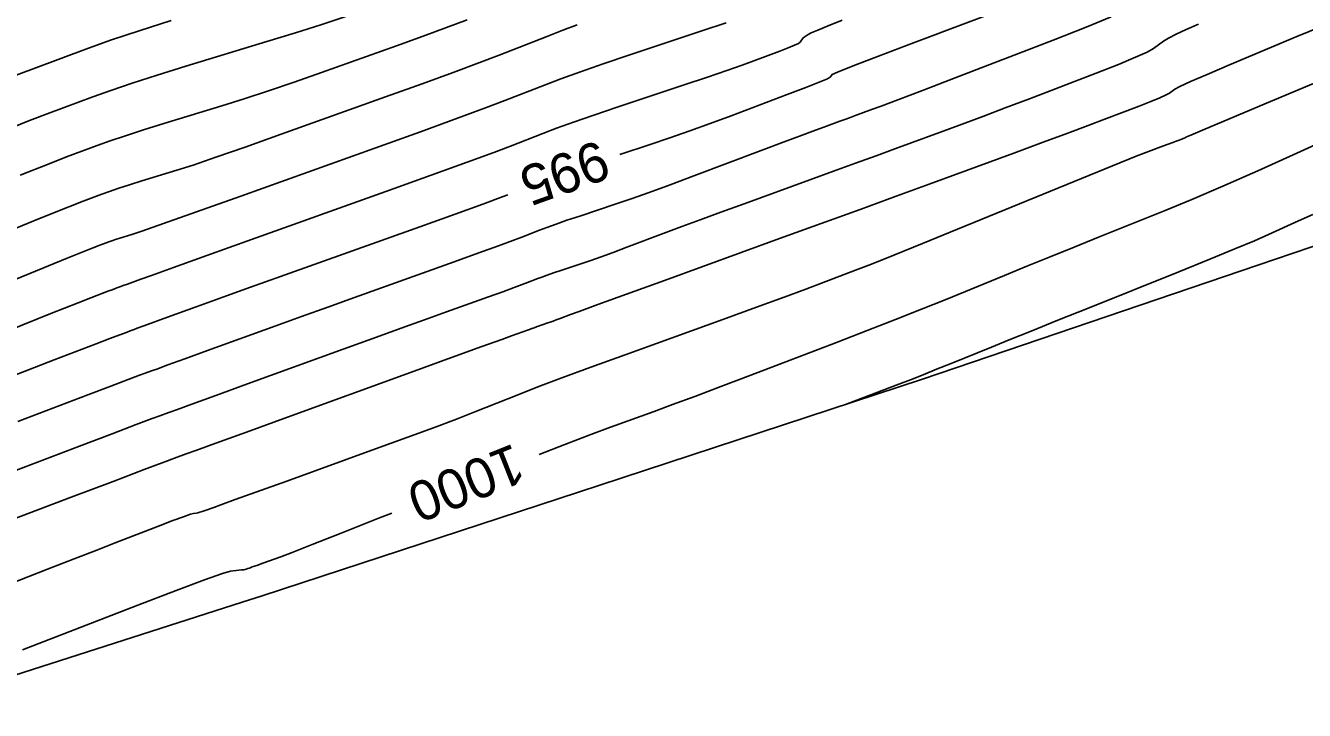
# Model space of a CAD drawing. Extents: x 2175772 to 2185556, y 721391 to 722853.
# Drawn here: x 2178632.3 to 2178722.5, y 721747 to 721795.3 of the extents above; entities that cross this region are included whole.
import ezdxf

# ---------------------------------------------------------------- set-up
doc = ezdxf.new("R2010")
doc.units = 0
for name, color, linetype in [('DT_X_Contour_Major', 7, 'Continuous'), ('DT_X_Contour_Minor', 7, 'Continuous'), ('DT_X_TIN_Hull', 7, 'Continuous')]:
    doc.layers.add(name, color=color, linetype=linetype)

msp = doc.modelspace()

# ---------------------------------------------------------------- linework, layer by layer
at = {"layer": 'DT_X_Contour_Major'}
for points in [[(2178660.661, 721798.004), (2178660.335, 721797.884), (2178659.194, 721797.473), (2178655.973, 721796.321), (2178654.649, 721795.861), (2178653.092, 721795.346), (2178651.302, 721794.775), (2178649.279, 721794.149), (2178643.573, 721792.406), (2178641.558, 721791.781), (2178639.793, 721791.214), (2178638.279, 721790.704), (2178637.014, 721790.251), (2178633.975, 721789.121), (2178632.542, 721788.572), (2178630.52, 721787.772)], [(2178702.475, 721796.913), (2178694.915, 721794.072), (2178692.429, 721793.132), (2178690.642, 721792.444), (2178689.553, 721792.006), (2178689.162, 721791.819), (2178689.053, 721791.657), (2178688.831, 721791.533), (2178688.248, 721791.285), (2178687.303, 721790.912), (2178685.998, 721790.415), (2178682.034, 721788.922), (2178680.563, 721788.376), (2178679.121, 721787.855), (2178677.71, 721787.361), (2178676.328, 721786.893), (2178674.191, 721786.181)], [(2178729.674, 721789.794), (2178721.955, 721786.277), (2178719.203, 721785.035), (2178716.736, 721783.947), (2178714.553, 721783.012), (2178712.654, 721782.23), (2178707.971, 721780.352), (2178706.238, 721779.655), (2178704.552, 721778.973), (2178702.912, 721778.306), (2178701.319, 721777.655), (2178697.132, 721775.939), (2178695.476, 721775.268), (2178693.647, 721774.542), (2178691.645, 721773.761), (2178689.47, 721772.924), (2178683.44, 721770.621), (2178681.318, 721769.813), (2178679.472, 721769.117), (2178677.902, 721768.532), (2178676.61, 721768.059), (2178673.533, 721766.947), (2178672.148, 721766.432), (2178670.302, 721765.724), (2178668.509, 721765.022)], [(2178666.288, 721783.342), (2178665.963, 721783.218), (2178664.525, 721782.69), (2178662.567, 721781.981), (2178660.089, 721781.091), (2178650.256, 721777.572), (2178648.14, 721776.813), (2178646.44, 721776.202), (2178645.155, 721775.737), (2178642.282, 721774.694), (2178640.615, 721774.089), (2178640.147, 721773.919), (2178639.923, 721773.838), (2178639.65, 721773.739), (2178639.423, 721773.654), (2178638.214, 721773.197), (2178637.234, 721772.825), (2178634.285, 721771.705), (2178632.884, 721771.163), (2178630.893, 721770.378)], [(2178658.1, 721760.886), (2178657.223, 721760.537), (2178654.539, 721759.47), (2178652.485, 721758.659), (2178651.061, 721758.103), (2178650.269, 721757.803), (2178648.997, 721757.344), (2178648.574, 721757.191), (2178648.259, 721757.077), (2178648.051, 721757.002), (2178647.951, 721756.966), (2178647.828, 721756.922), (2178647.761, 721756.904), (2178647.651, 721756.885), (2178647.499, 721756.865), (2178647.305, 721756.843), (2178646.731, 721756.783), (2178646.161, 721756.615), (2178644.881, 721756.159), (2178642.892, 721755.414), (2178640.192, 721754.38), (2178632.048, 721751.237)]]:
    msp.add_lwpolyline(points, dxfattribs=at)
at = {"layer": 'DT_X_Contour_Minor'}
for points in [[(2178723.694, 721795.222), (2178721.965, 721794.511), (2178717.199, 721792.505), (2178715.617, 721791.834), (2178714.448, 721791.325), (2178713.69, 721790.98), (2178713.344, 721790.796), (2178712.972, 721790.524), (2178712.733, 721790.39), (2178712.295, 721790.192), (2178711.658, 721789.929), (2178710.823, 721789.602), (2178708.329, 721788.645), (2178707.232, 721788.228), (2178705.808, 721787.696), (2178704.058, 721787.048), (2178701.983, 721786.285), (2178696.014, 721784.096), (2178693.675, 721783.24), (2178691.135, 721782.313), (2178688.395, 721781.315), (2178685.455, 721780.246), (2178677.346, 721777.303), (2178674.65, 721776.324), (2178672.645, 721775.595), (2178671.332, 721775.115), (2178670.709, 721774.886), (2178669.97, 721774.608), (2178669.708, 721774.51), (2178669.479, 721774.426), (2178669.282, 721774.356), (2178669.116, 721774.299), (2178668.718, 721774.167), (2178668.578, 721774.12), (2178668.457, 721774.078), (2178668.357, 721774.042), (2178668.275, 721774.011), (2178668.083, 721773.936), (2178667.983, 721773.898), (2178667.826, 721773.84), (2178667.612, 721773.762), (2178667.341, 721773.665), (2178666.542, 721773.379), (2178665.873, 721773.138), (2178664.464, 721772.627), (2178662.315, 721771.848), (2178659.427, 721770.8), (2178650.738, 721767.646), (2178647.848, 721766.597), (2178645.696, 721765.815), (2178644.281, 721765.302), (2178643.603, 721765.055), (2178642.778, 721764.756), (2178642.09, 721764.499), (2178640.642, 721763.953), (2178638.436, 721763.117), (2178635.471, 721761.992), (2178626.552, 721758.605)], [(2178681.683, 721795.471), (2178679.972, 721794.901), (2178674.827, 721793.188), (2178673.008, 721792.575), (2178671.409, 721792.02), (2178670.031, 721791.522), (2178668.873, 721791.082), (2178666.079, 721789.987), (2178664.719, 721789.469), (2178662.737, 721788.737), (2178660.131, 721787.792), (2178656.902, 721786.632), (2178647.461, 721783.254), (2178644.324, 721782.133), (2178641.993, 721781.306), (2178640.468, 721780.771), (2178639.75, 721780.528), (2178638.91, 721780.271), (2178638.613, 721780.179), (2178638.354, 721780.096), (2178638.131, 721780.021), (2178637.944, 721779.954), (2178637.497, 721779.788), (2178636.838, 721779.524), (2178635.198, 721778.859), (2178632.575, 721777.791), (2178628.971, 721776.321)], [(2178715.024, 721795.386), (2178714.142, 721795.004), (2178713.436, 721794.677), (2178712.907, 721794.403), (2178712.555, 721794.184), (2178711.852, 721793.67), (2178711.4, 721793.417), (2178710.574, 721793.042), (2178709.371, 721792.546), (2178707.794, 721791.929), (2178703.087, 721790.122), (2178701.383, 721789.47), (2178699.801, 721788.871), (2178698.342, 721788.325), (2178697.005, 721787.83), (2178693.603, 721786.583), (2178692.27, 721786.095), (2178690.823, 721785.567), (2178689.261, 721784.998), (2178687.586, 721784.389), (2178682.964, 721782.711), (2178681.319, 721782.113), (2178679.85, 721781.574), (2178678.556, 721781.095), (2178677.438, 721780.677), (2178674.691, 721779.643), (2178673.72, 721779.28), (2178672.868, 721778.968), (2178672.135, 721778.707), (2178671.52, 721778.497), (2178670.039, 721778.004), (2178669.52, 721777.829), (2178669.073, 721777.675), (2178668.698, 721777.54), (2178668.395, 721777.425), (2178667.682, 721777.146), (2178667.31, 721777.004), (2178666.725, 721776.79), (2178665.93, 721776.502), (2178664.923, 721776.14), (2178661.957, 721775.079), (2178660.667, 721774.616), (2178659.023, 721774.023), (2178657.024, 721773.299), (2178654.67, 721772.445), (2178647.919, 721769.995), (2178645.675, 721769.18), (2178644.002, 721768.573), (2178642.903, 721768.174), (2178642.376, 721767.983), (2178641.736, 721767.75), (2178641.201, 721767.551), (2178640.076, 721767.126), (2178638.362, 721766.477), (2178636.058, 721765.603), (2178629.13, 721762.972)], [(2178671.176, 721795.334), (2178670.16, 721794.95), (2178668.992, 721794.497), (2178665.678, 721793.197), (2178664.245, 721792.647), (2178662.432, 721791.972), (2178660.239, 721791.171), (2178657.666, 721790.246), (2178650.299, 721787.61), (2178647.766, 721786.709), (2178645.693, 721785.986), (2178644.08, 721785.439), (2178642.926, 721785.068), (2178640.464, 721784.316), (2178639.595, 721784.047), (2178638.834, 721783.802), (2178638.18, 721783.582), (2178637.634, 721783.386), (2178636.323, 721782.899), (2178635.308, 721782.5), (2178633.247, 721781.67), (2178630.141, 721780.409)], [(2178689.867, 721795.661), (2178688.881, 721795.262), (2178688.155, 721794.961), (2178687.689, 721794.76), (2178687.482, 721794.658), (2178687.125, 721794.414), (2178686.924, 721794.116), (2178686.801, 721794.028), (2178686.518, 721793.892), (2178686.074, 721793.707), (2178685.47, 721793.473), (2178683.646, 721792.786), (2178682.825, 721792.487), (2178681.733, 721792.105), (2178680.368, 721791.639), (2178678.732, 721791.091), (2178674.004, 721789.517), (2178672.346, 721788.959), (2178670.919, 721788.464), (2178669.721, 721788.034), (2178668.753, 721787.668), (2178666.48, 721786.777), (2178665.29, 721786.325), (2178663.425, 721785.64), (2178660.886, 721784.72), (2178657.672, 721783.567), (2178648.201, 721780.178), (2178645.05, 721779.051), (2178642.699, 721778.209), (2178641.148, 721777.653), (2178640.398, 721777.383), (2178639.464, 721777.044), (2178639.153, 721776.931), (2178638.921, 721776.847), (2178638.769, 721776.791), (2178638.696, 721776.765), (2178638.608, 721776.733), (2178638.534, 721776.705), (2178638.378, 721776.646), (2178638.141, 721776.557), (2178637.822, 721776.436), (2178636.863, 721776.071), (2178635.98, 721775.724), (2178634.052, 721774.953), (2178631.079, 721773.76)], [(2178642.54, 721795.649), (2178640.273, 721794.92), (2178638.328, 721794.265), (2178636.704, 721793.684), (2178632.801, 721792.232), (2178631.158, 721791.608)], [(2178708.852, 721795.892), (2178707.085, 721795.163), (2178704.765, 721794.256), (2178697.844, 721791.598), (2178695.533, 721790.712), (2178693.794, 721790.046), (2178692.625, 721789.601), (2178692.027, 721789.376), (2178691.192, 721789.07), (2178690.866, 721788.95), (2178690.511, 721788.82), (2178690.128, 721788.681), (2178689.716, 721788.532), (2178688.583, 721788.12), (2178687.988, 721787.901), (2178687.054, 721787.553), (2178685.78, 721787.075), (2178684.167, 721786.469), (2178679.412, 721784.678), (2178677.732, 721784.05), (2178676.257, 721783.511), (2178674.988, 721783.059), (2178673.924, 721782.695), (2178671.361, 721781.842), (2178670.462, 721781.539), (2178669.688, 721781.271), (2178669.039, 721781.038), (2178668.514, 721780.839), (2178667.281, 721780.356), (2178666.636, 721780.111), (2178665.625, 721779.74), (2178664.249, 721779.241), (2178662.506, 721778.616), (2178657.372, 721776.779), (2178655.462, 721776.094), (2178653.582, 721775.418), (2178651.732, 721774.75), (2178649.912, 721774.091), (2178645.101, 721772.345), (2178643.501, 721771.764), (2178642.309, 721771.331), (2178641.525, 721771.047), (2178641.15, 721770.91), (2178640.693, 721770.744), (2178640.312, 721770.602), (2178639.51, 721770.3), (2178638.288, 721769.837), (2178636.646, 721769.214), (2178631.707, 721767.338)], [(2178663.41, 721795.684), (2178661.967, 721795.144), (2178660.307, 721794.536), (2178658.43, 721793.859), (2178653.136, 721791.965), (2178651.208, 721791.285), (2178649.392, 721790.666), (2178647.691, 721790.107), (2178646.103, 721789.609), (2178642.019, 721788.361), (2178640.577, 721787.914), (2178639.313, 721787.508), (2178638.229, 721787.143), (2178637.324, 721786.819), (2178635.149, 721786.01), (2178633.925, 721785.536), (2178631.884, 721784.721)], [(2178726.317, 721792.546), (2178719.373, 721789.623), (2178717.092, 721788.663), (2178715.459, 721787.974), (2178714.473, 721787.556), (2178714.134, 721787.409), (2178714.092, 721787.378), (2178714.065, 721787.363), (2178714.016, 721787.341), (2178713.945, 721787.312), (2178713.851, 721787.275), (2178713.572, 721787.168), (2178713.429, 721787.114), (2178713.209, 721787.032), (2178712.536, 721786.785), (2178710.607, 721786.077), (2178698.01, 721780.913), (2178695.536, 721779.902), (2178693.512, 721779.082), (2178691.94, 721778.453), (2178690.818, 721778.015), (2178688.427, 721777.101), (2178687.319, 721776.685), (2178685.789, 721776.12), (2178683.836, 721775.407), (2178681.461, 721774.546), (2178674.563, 721772.053), (2178672.155, 721771.176), (2178670.102, 721770.419), (2178668.406, 721769.779), (2178667.067, 721769.257), (2178663.969, 721768.024), (2178662.66, 721767.513), (2178661.054, 721766.906), (2178659.151, 721766.203), (2178656.952, 721765.404), (2178650.693, 721763.144), (2178647.059, 721761.832), (2178646.036, 721761.463), (2178645.544, 721761.285), (2178644.938, 721761.066), (2178644.728, 721760.993), (2178644.556, 721760.939), (2178644.42, 721760.903), (2178644.321, 721760.885), (2178644.104, 721760.862), (2178643.89, 721760.799), (2178643.408, 721760.627), (2178642.659, 721760.347), (2178641.642, 721759.957), (2178638.576, 721758.774), (2178637.28, 721758.272), (2178635.691, 721757.655), (2178633.811, 721756.921), (2178625.457, 721753.653)], [(2178723.073, 721781.94), (2178722.065, 721781.495), (2178719.958, 721780.535), (2178718.971, 721780.101), (2178717.587, 721779.519), (2178715.807, 721778.789), (2178713.631, 721777.91), (2178707.301, 721775.371), (2178705.09, 721774.483), (2178703.206, 721773.725), (2178701.649, 721773.097), (2178700.419, 721772.599), (2178697.573, 721771.443), (2178696.541, 721771.027), (2178695.581, 721770.644), (2178694.692, 721770.294), (2178693.875, 721769.979), (2178690.226, 721768.583)]]:
    msp.add_lwpolyline(points, dxfattribs=at)
at = {"layer": 'DT_X_TIN_Hull'}
msp.add_lwpolyline([(2178623.731, 721746.955), (2178647.535, 721754.586), (2178648.95, 721755.04), (2178672.703, 721762.834), (2178695.543, 721770.328), (2178719.209, 721778.379), (2178742.875, 721786.431), (2178746.708, 721787.735), (2178770.443, 721795.584), (2178794.178, 721803.433), (2178795.878, 721803.995), (2178819.557, 721812.012), (2178837.71, 721818.159), (2178861.405, 721826.129), (2178885.1, 721834.1), (2178908.796, 721842.07), (2178932.491, 721850.041), (2178956.186, 721858.011), (2178979.881, 721865.982), (2179003.576, 721873.952)], dxfattribs=at)

# ---------------------------------------------------------------- texts
at = {"layer": 'DT_X_Contour_Major'}
for s, rotation, p in [('995', 199.76413, (2178672.779, 721787.245)), ('1000', 201.67062, (2178666.719, 721765.822))]:
    msp.add_text(s, height=2.8, rotation=rotation, dxfattribs=at).set_placement(p)

doc.saveas('drawing.dxf')
